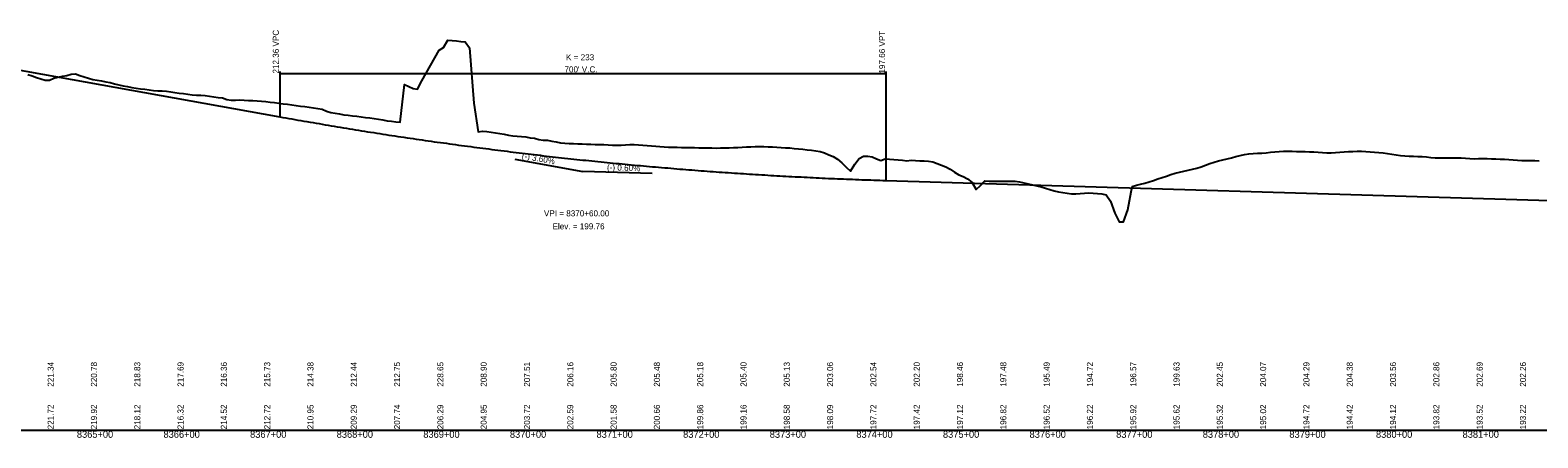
# Model space of a CAD drawing. Extents: x 1838386 to 1955906, y 719739 to 834437.
# Drawn here: x 1880653 to 1882394, y 758480 to 758951 of the extents above; entities that cross this region are included whole.
import ezdxf

# ---------------------------------------------------------------- set-up
doc = ezdxf.new("R2010")
doc.units = 0
for name, color, linetype in [('RD_DDB_GradeTX', 7, 'Continuous'), ('RD_DDB_Profile_EX', 7, 'Continuous'), ('RD_DDB_Profile_Lbl', 7, 'Continuous'), ('RD_DDB_Profile_PR', 7, 'Continuous'), ('RD_DDB_StaTX', 7, 'Continuous'), ('RD_DDB_StripGrade', 7, 'Continuous'), ('RD_DDB_VCLbl', 7, 'Continuous'), ('RD_GPK_Profile_Cell', 7, 'Continuous')]:
    doc.layers.add(name, color=color, linetype=linetype)

msp = doc.modelspace()

# ---------------------------------------------------------------- linework, layer by layer
at = {"layer": 'RD_DDB_GradeTX'}
for p in [(1881212.9, 758802.1), (1881371.6, 758785.5)]:
    msp.add_line(p, (1881291.6, 758787.9), dxfattribs=at)
at = {"layer": 'RD_DDB_Profile_EX'}
for points in [[(1880700.7, 758900), (1880705.7, 758900.4), (1880710.7, 758898.7), (1880715.7, 758897.1), (1880720.7, 758895.6), (1880725.7, 758894.2), (1880730.7, 758893.2), (1880735.7, 758892.3), (1880740.7, 758891.5), (1880745.7, 758890.4), (1880750.7, 758889.2), (1880755.7, 758888), (1880760.7, 758886.8), (1880765.7, 758885.8), (1880770.7, 758884.8), (1880775.7, 758883.9), (1880780.7, 758883.4), (1880785.7, 758882.8), (1880790.7, 758882.1), (1880795.7, 758881.5), (1880800.7, 758881.1), (1880805.7, 758880.8), (1880810.7, 758880.4), (1880815.7, 758879.8), (1880820.7, 758878.9), (1880825.7, 758878.4), (1880830.7, 758877.7), (1880835.7, 758877), (1880840.7, 758876.3), (1880845.7, 758876.1), (1880850.7, 758876.1), (1880855.7, 758875.4), (1880860.7, 758874.8), (1880865.7, 758874.1), (1880870.7, 758873.4), (1880875.7, 758872.7), (1880880.7, 758871.1), (1880885.7, 758870), (1880890.7, 758870.1), (1880895.7, 758870.4), (1880900.7, 758870.1), (1880905.7, 758869.8), (1880910.7, 758869.6), (1880915.7, 758869.4), (1880920.7, 758869), (1880925.7, 758868.5), (1880930.7, 758867.9), (1880935.7, 758867.3), (1880940.7, 758866.7), (1880945.7, 758866.1), (1880950.7, 758865.5), (1880955.7, 758864.8), (1880960.7, 758864.1), (1880965.7, 758863.3), (1880970.7, 758862.7), (1880975.7, 758862.1), (1880980.7, 758861.2), (1880985.7, 758860.4), (1880990.7, 758859.7), (1880995.7, 758857.5), (1881000.7, 758856), (1881005.7, 758855.1), (1881010.7, 758854.3), (1881015.7, 758853.3), (1881020.7, 758852.8), (1881025.7, 758852.2), (1881030.7, 758851.5), (1881035.7, 758850.8), (1881040.7, 758850.1), (1881045.7, 758849.6), (1881050.7, 758849), (1881055.7, 758848.3), (1881060.7, 758847.3), (1881065.7, 758846.3), (1881070.7, 758845.8), (1881075.7, 758845.2), (1881080.7, 758844.9), (1881085.7, 758888.2), (1881090.7, 758885.8), (1881095.7, 758883.5), (1881100.7, 758882.8), (1881105.7, 758892.3), (1881110.7, 758901.2), (1881115.7, 758910.1), (1881120.7, 758918.9), (1881125.7, 758927.8), (1881130.7, 758930.8), (1881135.7, 758939.4), (1881140.7, 758939.1), (1881145.7, 758938.5), (1881150.7, 758938), (1881155.7, 758937.7), (1881160.7, 758930.5), (1881165.7, 758866.7), (1881170.7, 758833.4), (1881175.7, 758834.5), (1881180.7, 758833.8), (1881185.7, 758833), (1881190.7, 758832.3), (1881195.7, 758831.5), (1881200.7, 758830.7)], [(1880650.7, 758899.8), (1880655.7, 758898.1), (1880660.7, 758896.3), (1880665.7, 758894.7), (1880670.7, 758893.1), (1880675.7, 758893.3), (1880680.7, 758895.6), (1880685.7, 758896.9), (1880690.7, 758898), (1880695.7, 758898.6), (1880700.7, 758900)], [(1881200.7, 758830.7), (1881205.7, 758829.9), (1881210.7, 758829.1), (1881215.7, 758828.5), (1881220.7, 758828), (1881225.7, 758827.6), (1881230.7, 758826.8), (1881235.7, 758826.2), (1881240.7, 758824.7), (1881245.7, 758824.1), (1881250.7, 758823.8), (1881255.7, 758822.9), (1881260.7, 758821.9), (1881265.7, 758821), (1881270.7, 758820.6), (1881275.7, 758820.2), (1881280.7, 758820), (1881285.7, 758819.8), (1881290.7, 758819.6), (1881295.7, 758819.5), (1881300.7, 758819.3), (1881305.7, 758819.1), (1881310.7, 758818.9), (1881315.7, 758818.8), (1881320.7, 758818.6), (1881325.7, 758818.2), (1881330.7, 758818.1), (1881335.7, 758818.3), (1881340.7, 758818.7), (1881345.7, 758819.1), (1881350.7, 758819), (1881355.7, 758818.6), (1881360.7, 758818.3), (1881365.7, 758817.9), (1881370.7, 758817.5), (1881375.7, 758817), (1881380.7, 758816.6), (1881385.7, 758816.2), (1881390.7, 758815.8), (1881395.7, 758815.8), (1881400.7, 758815.7), (1881405.7, 758815.6), (1881410.7, 758815.5), (1881415.7, 758815.4), (1881420.7, 758815.3), (1881425.7, 758815.2), (1881430.7, 758815.1), (1881435.7, 758814.9), (1881440.7, 758814.9), (1881445.7, 758814.8), (1881450.7, 758814.9), (1881455.7, 758815.1), (1881460.7, 758815.2), (1881465.7, 758815.3), (1881470.7, 758815.5), (1881475.7, 758815.8), (1881480.7, 758816.1), (1881485.7, 758816.3), (1881490.7, 758816.5), (1881495.7, 758816.7), (1881500.7, 758816.6), (1881505.7, 758816.3), (1881510.7, 758816.1), (1881515.7, 758815.8), (1881520.7, 758815.5), (1881525.7, 758815.2), (1881530.7, 758814.9), (1881535.7, 758814.5), (1881540.7, 758813.9), (1881545.7, 758813.4), (1881550.7, 758812.8), (1881555.7, 758812.2), (1881560.7, 758811.6), (1881565.7, 758810.7), (1881570.7, 758809.2), (1881575.7, 758807.1), (1881580.7, 758805), (1881585.7, 758802), (1881590.7, 758797.9), (1881595.7, 758792.8), (1881600.7, 758788.1), (1881605.7, 758796.1), (1881610.7, 758802.6), (1881615.7, 758805.4), (1881620.7, 758805.3), (1881625.7, 758804.5), (1881630.7, 758802.2), (1881635.7, 758800.4), (1881640.7, 758802.5), (1881645.7, 758802.1), (1881650.7, 758801.6), (1881655.7, 758801.1), (1881660.7, 758800.7), (1881665.7, 758800.2), (1881670.7, 758800.7), (1881675.7, 758800.5), (1881680.7, 758800.2), (1881685.7, 758799.9), (1881690.7, 758799.7), (1881695.7, 758799), (1881700.7, 758797.1)], [(1881700.7, 758797.1), (1881705.7, 758795.1), (1881710.7, 758793.1), (1881715.7, 758790.4), (1881720.7, 758786.8), (1881725.7, 758784), (1881730.7, 758781.9), (1881735.7, 758779.3), (1881740.7, 758775.6), (1881745.7, 758766.9), (1881750.7, 758771.7), (1881755.7, 758777), (1881760.7, 758776.5), (1881765.7, 758776.4), (1881770.7, 758776.4), (1881775.7, 758776.5), (1881780.7, 758776.5), (1881785.7, 758776.5), (1881790.7, 758776.6), (1881795.7, 758775.8), (1881800.7, 758774.6), (1881805.7, 758773.5), (1881810.7, 758772.3), (1881815.7, 758771.2), (1881820.7, 758769.9), (1881825.7, 758768.4), (1881830.7, 758766.9), (1881835.7, 758765.3), (1881840.7, 758764.3), (1881845.7, 758763.5), (1881850.7, 758762.7), (1881855.7, 758762), (1881860.7, 758761.9), (1881865.7, 758762.3), (1881870.7, 758762.7), (1881875.7, 758763), (1881880.7, 758762.8), (1881885.7, 758762.5), (1881890.7, 758761.9), (1881895.7, 758760.9), (1881900.7, 758753.6), (1881905.7, 758739.7), (1881910.7, 758729.5), (1881915.7, 758729.5), (1881920.7, 758743.5), (1881925.7, 758770.3), (1881930.7, 758771.8), (1881935.7, 758773.1), (1881940.7, 758774.4), (1881945.7, 758775.7), (1881950.7, 758777.4), (1881955.7, 758779.1), (1881960.7, 758780.8), (1881965.7, 758782.5), (1881970.7, 758784.2), (1881975.7, 758785.9), (1881980.7, 758787.1), (1881985.7, 758788.2), (1881990.7, 758789.3), (1881995.7, 758790.3), (1882000.7, 758791.4), (1882005.7, 758793), (1882010.7, 758795), (1882015.7, 758796.8), (1882020.7, 758798.5), (1882025.7, 758800), (1882030.7, 758801.2), (1882035.7, 758802.3), (1882040.7, 758803.7), (1882045.7, 758804.9), (1882050.7, 758806.1), (1882055.7, 758807.2), (1882060.7, 758808.3), (1882065.7, 758808.7), (1882070.7, 758808.9), (1882075.7, 758809.1), (1882080.7, 758809.4), (1882085.7, 758810), (1882090.7, 758810.5), (1882095.7, 758810.9), (1882100.7, 758811.1), (1882105.7, 758811.1), (1882110.7, 758811.1), (1882115.7, 758810.9), (1882120.7, 758810.8), (1882125.7, 758810.7), (1882130.7, 758810.6), (1882135.7, 758810.3), (1882140.7, 758810), (1882145.7, 758809.7), (1882150.7, 758809.3), (1882155.7, 758809.2), (1882160.7, 758809.6), (1882165.7, 758809.9), (1882170.7, 758810.3), (1882175.7, 758810.7), (1882180.7, 758811), (1882185.7, 758811.2), (1882190.7, 758811.1), (1882195.7, 758811), (1882200.7, 758810.6)], [(1882200.7, 758810.6), (1882205.7, 758810.2), (1882210.7, 758809.8), (1882215.7, 758809.4), (1882220.7, 758808.7), (1882225.7, 758807.9), (1882230.7, 758807.1), (1882235.7, 758806.3), (1882240.7, 758805.7), (1882245.7, 758805.5), (1882250.7, 758805.3), (1882255.7, 758805.1), (1882260.7, 758804.9), (1882265.7, 758804.5), (1882270.7, 758804), (1882275.7, 758803.5), (1882280.7, 758803.4), (1882285.7, 758803.4), (1882290.7, 758803.4), (1882295.7, 758803.4), (1882300.7, 758803.4), (1882305.7, 758803.4), (1882310.7, 758803.2), (1882315.7, 758802.8), (1882320.7, 758802.5), (1882325.7, 758802.6), (1882330.7, 758802.6), (1882335.7, 758802.6), (1882340.7, 758802.5), (1882345.7, 758802.3), (1882350.7, 758802.1), (1882355.7, 758801.8), (1882360.7, 758801.6), (1882365.7, 758801.4), (1882370.7, 758800.8), (1882375.7, 758800.6), (1882380.7, 758800.5), (1882385.7, 758800.4), (1882390.7, 758800.3), (1882395.7, 758800.2)]]:
    msp.add_lwpolyline(points, dxfattribs=at)
at = {"layer": 'RD_DDB_Profile_PR'}
for p, q in [((1880431.6, 758942.7), (1880941.6, 758850.9)), ((1881641.6, 758777.4), (1883831.6, 758711.7))]:
    msp.add_line(p, q, dxfattribs=at)
msp.add_spline([(1880941.6, 758850.9), (1880955.6, 758848.4), (1880969.6, 758846), (1880983.6, 758843.6), (1880997.6, 758841.2), (1881011.6, 758838.8), (1881025.6, 758836.6), (1881039.6, 758834.3), (1881053.6, 758832.1), (1881067.6, 758829.9), (1881081.6, 758827.8), (1881095.6, 758825.7), (1881109.6, 758823.7), (1881123.6, 758821.7), (1881137.6, 758819.8), (1881151.6, 758817.8), (1881165.6, 758816), (1881179.6, 758814.2), (1881193.6, 758812.4), (1881207.6, 758810.6), (1881221.6, 758808.9), (1881235.6, 758807.3), (1881249.6, 758805.6), (1881263.6, 758804.1), (1881277.6, 758802.5), (1881291.6, 758801), (1881305.6, 758799.6), (1881319.6, 758798.2), (1881333.6, 758796.8), (1881347.6, 758795.5), (1881361.6, 758794.2), (1881375.6, 758793), (1881389.6, 758791.8), (1881403.6, 758790.6), (1881417.6, 758789.5), (1881431.6, 758788.4), (1881445.6, 758787.4), (1881459.6, 758786.4), (1881473.6, 758785.5), (1881487.6, 758784.6), (1881501.6, 758783.7), (1881515.6, 758782.9), (1881529.6, 758782.1), (1881543.6, 758781.4), (1881557.6, 758780.7), (1881571.6, 758780), (1881585.6, 758779.4), (1881599.6, 758778.9), (1881613.6, 758778.3), (1881627.6, 758777.9), (1881641.6, 758777.4)], degree=3, dxfattribs=at)
at = {"layer": 'RD_DDB_VCLbl'}
for p, q in [((1880941.6, 758903.4), (1880941.6, 758850.9)), ((1880941.6, 758900.9), (1881641.6, 758900.9)), ((1881641.6, 758903.4), (1881641.6, 758777.4))]:
    msp.add_line(p, q, dxfattribs=at)
at = {"layer": 'RD_GPK_Profile_Cell'}
msp.add_line((1877681.6, 758489.1), (1884181.6, 758489.1), dxfattribs=at)

# ---------------------------------------------------------------- texts
at = {"layer": 'RD_DDB_GradeTX'}
for s, rotation, p in [('(-) 3.60%', 349.796, (1881220.8, 758802.7)), ('(-) 0.60%', 358.2816, (1881319.4, 758789.1))]:
    msp.add_text(s, height=7, rotation=rotation, dxfattribs=at).set_placement(p)
at = {"layer": 'RD_DDB_Profile_Lbl'}
for s, p in [('VPI = 8370+60.00', (1881246.7, 758735.9)), ('Elev. = 199.76', (1881256.6, 758720.9))]:
    msp.add_text(s, height=7, dxfattribs=at).set_placement(p)
at = {"layer": 'RD_DDB_StaTX'}
for s, p in [('8365+00', (1880707.4, 758480.1)), ('8366+00', (1880807.4, 758480.1)), ('8367+00', (1880907.4, 758480.1)), ('8368+00', (1881007.4, 758480.1)), ('8369+00', (1881107.4, 758480.1)), ('8370+00', (1881207.4, 758480.1)), ('8371+00', (1881307.4, 758480.1)), ('8372+00', (1881407.4, 758480.1)), ('8373+00', (1881507.4, 758480.1)), ('8374+00', (1881607.4, 758480.1)), ('8375+00', (1881707.4, 758480.1)), ('8376+00', (1881807.4, 758480.1)), ('8377+00', (1881907.4, 758480.1)), ('8378+00', (1882007.4, 758480.1)), ('8379+00', (1882107.4, 758480.1)), ('8380+00', (1882207.4, 758480.1)), ('8381+00', (1882307.4, 758480.1))]:
    msp.add_text(s, height=8, dxfattribs=at).set_placement(p)
at = {"layer": 'RD_DDB_StripGrade'}
for s, p in [('212.36 VPC', (1880940.6, 758900.9)), ('197.66 VPT', (1881640.6, 758900.9)), ('221.34', (1880680.6, 758539.1)), ('220.78', (1880730.6, 758539.1)), ('218.83', (1880780.6, 758539.1)), ('217.69', (1880830.6, 758539.1)), ('216.36', (1880880.6, 758539.1)), ('215.73', (1880930.6, 758539.1)), ('214.38', (1880980.6, 758539.1)), ('212.44', (1881030.6, 758539.1)), ('212.75', (1881080.6, 758539.1)), ('228.65', (1881130.6, 758539.1)), ('208.90', (1881180.6, 758539.1)), ('207.51', (1881230.6, 758539.1)), ('206.16', (1881280.6, 758539.1)), ('205.80', (1881330.6, 758539.1)), ('205.48', (1881380.6, 758539.1)), ('205.18', (1881430.6, 758539.1)), ('205.40', (1881480.6, 758539.1)), ('205.13', (1881530.6, 758539.1)), ('203.06', (1881580.6, 758539.1)), ('202.54', (1881630.6, 758539.1)), ('202.20', (1881680.6, 758539.1)), ('198.46', (1881730.6, 758539.1)), ('197.48', (1881780.6, 758539.1)), ('195.49', (1881830.6, 758539.1)), ('194.72', (1881880.6, 758539.1)), ('196.57', (1881930.6, 758539.1)), ('199.63', (1881980.6, 758539.1)), ('202.45', (1882030.6, 758539.1)), ('204.07', (1882080.6, 758539.1)), ('204.29', (1882130.6, 758539.1)), ('204.38', (1882180.6, 758539.1)), ('203.56', (1882230.6, 758539.1)), ('202.86', (1882280.6, 758539.1)), ('202.69', (1882330.6, 758539.1)), ('202.26', (1882380.6, 758539.1)), ('221.72', (1880680.6, 758489.9)), ('219.92', (1880730.6, 758489.9)), ('218.12', (1880780.6, 758489.9)), ('216.32', (1880830.6, 758489.9)), ('214.52', (1880880.6, 758489.9)), ('212.72', (1880930.6, 758489.9)), ('210.95', (1880980.6, 758489.9)), ('209.29', (1881030.6, 758489.9)), ('207.74', (1881080.6, 758489.9)), ('206.29', (1881130.6, 758489.9)), ('204.95', (1881180.6, 758489.9)), ('203.72', (1881230.6, 758489.9)), ('202.59', (1881280.6, 758489.9)), ('201.58', (1881330.6, 758489.9)), ('200.66', (1881380.6, 758489.9)), ('199.86', (1881430.6, 758489.9)), ('199.16', (1881480.6, 758489.9)), ('198.58', (1881530.6, 758489.9)), ('198.09', (1881580.6, 758489.9)), ('197.72', (1881630.6, 758489.9)), ('197.42', (1881680.6, 758489.9)), ('197.12', (1881730.6, 758489.9)), ('196.82', (1881780.6, 758489.9)), ('196.52', (1881830.6, 758489.9)), ('196.22', (1881880.6, 758489.9)), ('195.92', (1881930.6, 758489.9)), ('195.62', (1881980.6, 758489.9)), ('195.32', (1882030.6, 758489.9)), ('195.02', (1882080.6, 758489.9)), ('194.72', (1882130.6, 758489.9)), ('194.42', (1882180.6, 758489.9)), ('194.12', (1882230.6, 758489.9)), ('193.82', (1882280.6, 758489.9)), ('193.52', (1882330.6, 758489.9)), ('193.22', (1882380.6, 758489.9))]:
    msp.add_text(s, height=7, rotation=90, dxfattribs=at).set_placement(p)
at = {"layer": 'RD_DDB_VCLbl'}
for s, p in [('K = 233', (1881272.2, 758916.2)), ("700' V.C.", (1881270.4, 758902.2))]:
    msp.add_text(s, height=7, dxfattribs=at).set_placement(p)

doc.saveas('drawing.dxf')
